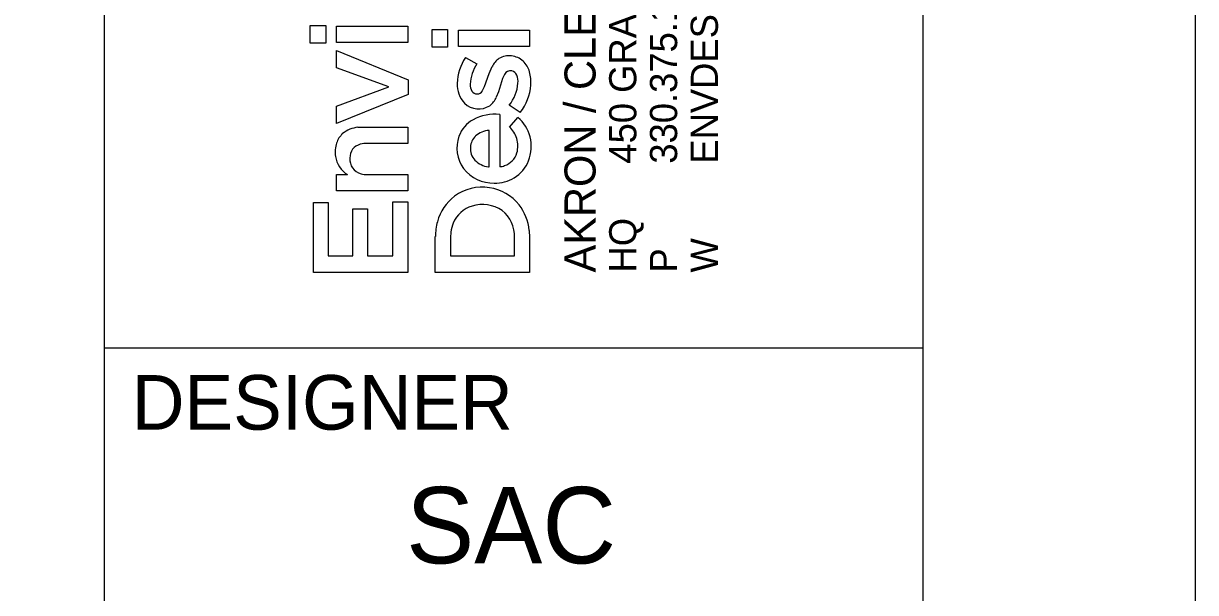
# Model space of a CAD drawing. Extents: x -0.4 to 34, y 0 to 22.
# Drawn here: x 31.851 to 34, y 2.552 to 3.594 of the extents above; entities that cross this region are included whole.
import ezdxf

# ---------------------------------------------------------------- set-up
doc = ezdxf.new("R2010")
doc.units = 0
for name, color, linetype in [('SH_Border', 7, 'Continuous'), ('SH_Cut_Line', 7, 'Continuous'), ('SH_Data', 7, 'Continuous')]:
    doc.layers.add(name, color=color, linetype=linetype)

msp = doc.modelspace()

# ---------------------------------------------------------------- linework, layer by layer
at = {"layer": 'SH_Border'}
for p, q in [((32, 0.5), (32, 21.5)), ((32, 3), (33.5, 3))]:
    msp.add_line(p, q, dxfattribs=at)
msp.add_lwpolyline([(1.5, 21.5), (33.5, 21.5), (33.5, 0.5), (1.5, 0.5)], close=True, dxfattribs=at)
at = {"layer": 'SH_Cut_Line'}
msp.add_lwpolyline([(0, 0), (34, 0), (34, 22), (0, 22)], close=True, dxfattribs=at)
at = {"layer": 'SH_Data'}
for p, q in [((32.3771, 3.5582), (32.3771, 3.5903)), ((32.3771, 3.5903), (32.4054, 3.5903)), ((32.4054, 3.5903), (32.4054, 3.5582)), ((32.4254, 3.5594), (32.4254, 3.5893)), ((32.4254, 3.5893), (32.5557, 3.5893)), ((32.5557, 3.5893), (32.5557, 3.5594)), ((32.6005, 3.5511), (32.6005, 3.5832)), ((32.6005, 3.5832), (32.6289, 3.5832)), ((32.6289, 3.5832), (32.6289, 3.5511)), ((32.6489, 3.5523), (32.6489, 3.5822)), ((32.6489, 3.5822), (32.7792, 3.5822)), ((32.7792, 3.5822), (32.7792, 3.5523)), ((32.4054, 3.5582), (32.3771, 3.5582)), ((32.5557, 3.5594), (32.4254, 3.5594)), ((32.6289, 3.5511), (32.6005, 3.5511)), ((32.7792, 3.5523), (32.6489, 3.5523)), ((32.4254, 3.5133), (32.4254, 3.5446)), ((32.4254, 3.5446), (32.5567, 3.4913)), ((32.6615, 3.5321), (32.6827, 3.5203)), ((32.5212, 3.478), (32.4254, 3.5133)), ((32.6967, 3.4787), (32.7048, 3.5026)), ((32.7048, 3.5026), (32.7104, 3.5153)), ((32.5567, 3.4913), (32.5567, 3.4644)), ((32.7298, 3.4933), (32.7221, 3.4688)), ((32.7334, 3.501), (32.7298, 3.4933)), ((32.4254, 3.4429), (32.5212, 3.478)), ((32.5567, 3.4644), (32.4254, 3.4109)), ((32.693, 3.4712), (32.6967, 3.4787)), ((32.7221, 3.4688), (32.7182, 3.4592)), ((32.4254, 3.4109), (32.4254, 3.4429)), ((32.7621, 3.4314), (32.742, 3.4447)), ((32.7245, 3.4275), (32.7246, 3.3319)), ((32.7423, 3.4046), (32.7577, 3.422)), ((32.4644, 3.404), (32.4729, 3.4044)), ((32.4729, 3.4044), (32.5557, 3.4044)), ((32.5557, 3.4044), (32.5557, 3.3746)), ((32.7049, 3.3318), (32.7049, 3.3983)), ((32.5557, 3.3746), (32.4814, 3.3746)), ((32.7036, 3.3317), (32.7049, 3.3318)), ((32.4254, 3.2875), (32.4254, 3.3173)), ((32.4254, 3.3173), (32.4455, 3.3173)), ((32.4822, 3.3173), (32.5557, 3.3173)), ((32.5557, 3.3173), (32.5557, 3.2876)), ((32.5557, 3.2876), (32.4254, 3.2875)), ((32.383, 3.1379), (32.383, 3.266)), ((32.383, 3.266), (32.4101, 3.266)), ((32.4101, 3.266), (32.4101, 3.1683)), ((32.5286, 3.1683), (32.5286, 3.2672)), ((32.5286, 3.2672), (32.5557, 3.2672)), ((32.5557, 3.2672), (32.5557, 3.1379)), ((32.455, 3.1683), (32.455, 3.2549)), ((32.455, 3.2549), (32.4822, 3.2549)), ((32.4822, 3.2549), (32.4822, 3.1683)), ((32.6064, 3.138), (32.6064, 3.204)), ((32.6347, 3.2118), (32.6341, 3.2023)), ((32.6341, 3.2023), (32.6341, 3.1684)), ((32.7515, 3.1683), (32.7515, 3.2024)), ((32.7785, 3.215), (32.7792, 3.2021)), ((32.7792, 3.2021), (32.7792, 3.138)), ((32.4101, 3.1683), (32.455, 3.1683)), ((32.4822, 3.1683), (32.5286, 3.1683)), ((32.6341, 3.1684), (32.7515, 3.1683)), ((32.5557, 3.1379), (32.383, 3.1379)), ((32.7792, 3.138), (32.6064, 3.138))]:
    msp.add_line(p, q, dxfattribs=at)
for points in [[(32.3771, 3.5582), (32.3771, 3.5903), (32.4054, 3.5903), (32.4054, 3.5582)], [(32.4254, 3.5594), (32.4254, 3.5893), (32.5557, 3.5893), (32.5557, 3.5594)], [(32.6005, 3.5511), (32.6005, 3.5832), (32.6289, 3.5832), (32.6289, 3.5511)], [(32.6489, 3.5523), (32.6489, 3.5822), (32.7792, 3.5822), (32.7792, 3.5523)], [(32.4254, 3.4109), (32.4254, 3.4429), (32.5212, 3.478), (32.4254, 3.5133), (32.4254, 3.5446), (32.5567, 3.4913), (32.5567, 3.4644)], [(32.383, 3.1379), (32.383, 3.266), (32.4101, 3.266), (32.4101, 3.1683), (32.455, 3.1683), (32.455, 3.2549), (32.4822, 3.2549), (32.4822, 3.1683), (32.5286, 3.1683), (32.5286, 3.2672), (32.5557, 3.2672), (32.5557, 3.1379)]]:
    msp.add_lwpolyline(points, close=True, dxfattribs=at)
for points in [[(32.6615, 3.5321), (32.6827, 3.5203)], [(32.693, 3.4712), (32.6967, 3.4787), (32.7048, 3.5026), (32.7104, 3.5153)], [(32.7334, 3.501), (32.7298, 3.4933), (32.7221, 3.4688), (32.7182, 3.4592)], [(32.7621, 3.4314), (32.742, 3.4447)], [(32.7245, 3.4275), (32.7246, 3.3319)], [(32.7423, 3.4046), (32.7577, 3.422)], [(32.4644, 3.404), (32.4729, 3.4044), (32.5557, 3.4044), (32.5557, 3.3746), (32.4814, 3.3746)], [(32.7036, 3.3317), (32.7049, 3.3318), (32.7049, 3.3983)], [(32.4254, 3.2875), (32.4254, 3.3173), (32.4455, 3.3173)], [(32.4822, 3.3173), (32.5557, 3.3173), (32.5557, 3.2876), (32.4254, 3.2875)], [(32.7785, 3.215), (32.7792, 3.2021), (32.7792, 3.138), (32.6064, 3.138)], [(32.6064, 3.138), (32.6064, 3.204)], [(32.6347, 3.2118), (32.6341, 3.2023), (32.6341, 3.1684), (32.7515, 3.1683), (32.7515, 3.2024)]]:
    msp.add_lwpolyline(points, dxfattribs=at)
for centre, radius, start, end in [((32.7364, 3.4826), 0.0897, 146.531, 178.7571), ((32.7364, 3.4826), 0.0897, 146.531, 178.7571), ((32.7466, 3.4971), 0.0405, 125.5118, 153.4159), ((32.7466, 3.4971), 0.0405, 125.5118, 153.4159), ((32.7406, 3.5026), 0.0326, 80.1719, 122.5197), ((32.7406, 3.5026), 0.0326, 80.1719, 122.5197), ((32.7428, 3.4982), 0.0367, 47.7934, 84.6892), ((32.7428, 3.4982), 0.0367, 47.7934, 84.6892), ((32.7379, 3.4946), 0.0427, 14.9966, 46.2063), ((32.7379, 3.4946), 0.0427, 14.9966, 46.2063), ((32.7452, 3.4789), 0.0749, 146.5112, 176.9101), ((32.7452, 3.4789), 0.0749, 146.5112, 176.9101), ((32.7438, 3.4963), 0.0114, 76.6609, 155.7053), ((32.7438, 3.4963), 0.0114, 76.6609, 155.7053), ((32.744, 3.4951), 0.0126, 21.5098, 78.5262), ((32.744, 3.4951), 0.0126, 21.5098, 78.5262), ((32.7104, 3.4867), 0.0712, 355.8306, 15.3914), ((32.7104, 3.4867), 0.0712, 355.8306, 15.3914), ((32.6967, 3.4824), 0.0501, 177.5366, 222.7932), ((32.6967, 3.4824), 0.0501, 177.5366, 222.7932), ((32.6931, 3.4823), 0.0228, 178.4747, 211.0868), ((32.6931, 3.4823), 0.0228, 178.4747, 211.0868), ((32.6825, 3.4915), 0.0757, 321.811, 354.7969), ((32.6825, 3.4915), 0.0757, 321.811, 354.7969), ((32.7259, 3.4877), 0.0321, 354.5726, 22.068), ((32.7259, 3.4877), 0.0321, 354.5726, 22.068), ((32.6895, 3.4882), 0.0922, 321.9777, 355.8738), ((32.6895, 3.4882), 0.0922, 321.9777, 355.8738), ((32.6833, 3.4767), 0.0115, 212.2368, 268.3777), ((32.6833, 3.4767), 0.0115, 212.2368, 268.3777), ((32.6834, 3.4759), 0.0107, 267.716, 333.7337), ((32.6834, 3.4759), 0.0107, 267.716, 333.7337), ((32.686, 3.4753), 0.0375, 225.9854, 302.4797), ((32.686, 3.4753), 0.0375, 225.9854, 302.4797), ((32.681, 3.4758), 0.0408, 308.0877, 335.9874), ((32.681, 3.4758), 0.0408, 308.0877, 335.9874), ((32.7024, 3.3691), 0.0558, 118.8308, 160.6244), ((32.7024, 3.3691), 0.0558, 118.8308, 160.6244), ((32.7152, 3.3441), 0.0838, 83.615, 118.2876), ((32.7152, 3.3441), 0.0838, 83.615, 118.2876), ((32.7174, 3.3717), 0.0644, 13.5336, 51.3615), ((32.7174, 3.3717), 0.0644, 13.5336, 51.3615), ((32.4687, 3.3543), 0.0499, 94.9696, 130.2225), ((32.4687, 3.3543), 0.0499, 94.9696, 130.2225), ((32.7079, 3.3561), 0.0424, 94.008, 130.8817), ((32.7079, 3.3561), 0.0424, 94.008, 130.8817), ((32.7038, 3.3656), 0.0549, 19.0357, 45.4406), ((32.7038, 3.3656), 0.0549, 19.0357, 45.4406), ((32.4787, 3.3582), 0.056, 162.2736, 187.7919), ((32.4787, 3.3582), 0.056, 162.2736, 187.7919), ((32.4635, 3.3626), 0.0402, 132.2219, 161.6818), ((32.4635, 3.3626), 0.0402, 132.2219, 161.6818), ((32.4811, 3.3286), 0.046, 89.6049, 105.3284), ((32.4811, 3.3286), 0.046, 89.6049, 105.3284), ((32.7104, 3.3661), 0.0644, 160.5201, 215.7831), ((32.7104, 3.3661), 0.0644, 160.5201, 215.7831), ((32.7005, 3.3663), 0.0298, 132.9851, 177.179), ((32.7005, 3.3663), 0.0298, 132.9851, 177.179), ((32.7107, 3.3697), 0.047, 344.6059, 17.007), ((32.7107, 3.3697), 0.047, 344.6059, 17.007), ((32.7064, 3.3692), 0.0758, 339.3542, 13.3785), ((32.7064, 3.3692), 0.0758, 339.3542, 13.3785), ((32.4748, 3.3487), 0.025, 103.6865, 182.2187), ((32.4748, 3.3487), 0.025, 103.6865, 182.2187), ((32.7017, 3.365), 0.0311, 175.0013, 223.283), ((32.7017, 3.365), 0.0311, 175.0013, 223.283), ((32.7224, 3.3671), 0.035, 288.0077, 343.5508), ((32.7224, 3.3671), 0.035, 288.0077, 343.5508), ((32.4703, 3.358), 0.0476, 188.962, 238.7037), ((32.4703, 3.358), 0.0476, 188.962, 238.7037), ((32.4773, 3.3456), 0.0276, 175.5854, 255.1439), ((32.4773, 3.3456), 0.0276, 175.5854, 255.1439), ((32.7089, 3.3736), 0.0423, 225.0619, 262.7974), ((32.7089, 3.3736), 0.0423, 225.0619, 262.7974), ((32.7247, 3.3522), 0.0202, 269.7003, 294.8711), ((32.7247, 3.3522), 0.0202, 269.7003, 294.8711), ((32.7189, 3.3652), 0.0626, 300.9427, 338.7323), ((32.7189, 3.3652), 0.0626, 300.9427, 338.7323), ((32.4818, 3.3595), 0.0422, 254.0916, 270.5284), ((32.4818, 3.3595), 0.0422, 254.0916, 270.5284), ((32.7125, 3.3705), 0.0687, 217.7452, 271.6543), ((32.7125, 3.3705), 0.0687, 217.7452, 271.6543), ((32.7155, 3.3724), 0.0706, 269.2048, 300.3341), ((32.7155, 3.3724), 0.0706, 269.2048, 300.3341), ((32.6923, 3.2079), 0.0864, 81.194, 125.9984), ((32.6923, 3.2079), 0.0864, 81.194, 125.9984), ((32.6946, 3.2113), 0.0827, 37.8521, 82.402), ((32.6946, 3.2113), 0.0827, 37.8521, 82.402), ((32.6939, 3.2089), 0.0865, 127.2362, 165.148), ((32.6939, 3.2089), 0.0865, 127.2362, 165.148), ((32.6889, 3.2078), 0.054, 106.1881, 157.3861), ((32.6889, 3.2078), 0.054, 106.1881, 157.3861), ((32.6928, 3.1986), 0.0639, 55.6727, 107.2093), ((32.6928, 3.1986), 0.0639, 55.6727, 107.2093), ((32.6929, 3.205), 0.0587, 357.4662, 52.2665), ((32.6929, 3.205), 0.0587, 357.4662, 52.2665), ((32.6859, 3.2057), 0.0931, 5.7333, 37.304), ((32.6859, 3.2057), 0.0931, 5.7333, 37.304), ((32.7143, 3.2028), 0.1078, 164.7861, 179.3704), ((32.7143, 3.2028), 0.1078, 164.7861, 179.3704), ((32.6983, 3.2039), 0.0641, 157.3571, 172.9275), ((32.6983, 3.2039), 0.0641, 157.3571, 172.9275)]:
    msp.add_arc(centre, radius, start, end, dxfattribs=at)

# ---------------------------------------------------------------- texts
for s, height, p in [('450 GRANT ST., AKRON, OH  44311', 0.049846, (32.9749, 3.3374)), ('AKRON / CLEVELAND / COLUMBUS', 0.056969, (32.9001, 3.138)), ('ENVDESIGNGROUP.COM', 0.049846, (33.1244, 3.3374)), ('330.375.1390', 0.049846, (33.0497, 3.3374)), ('HQ ', 0.04985, (32.9749, 3.138)), ('W', 0.0498, (33.1244, 3.138)), ('P', 0.0498, (33.0497, 3.138))]:
    msp.add_text(s, height=height, rotation=90, dxfattribs=at).set_placement(p)
for s, height, p in [('DESIGNER', 0.1, (32.05, 2.85)), ('SAC', 0.14, (32.5528, 2.605))]:
    msp.add_text(s, height=height, dxfattribs=at).set_placement(p)

doc.saveas('drawing.dxf')
